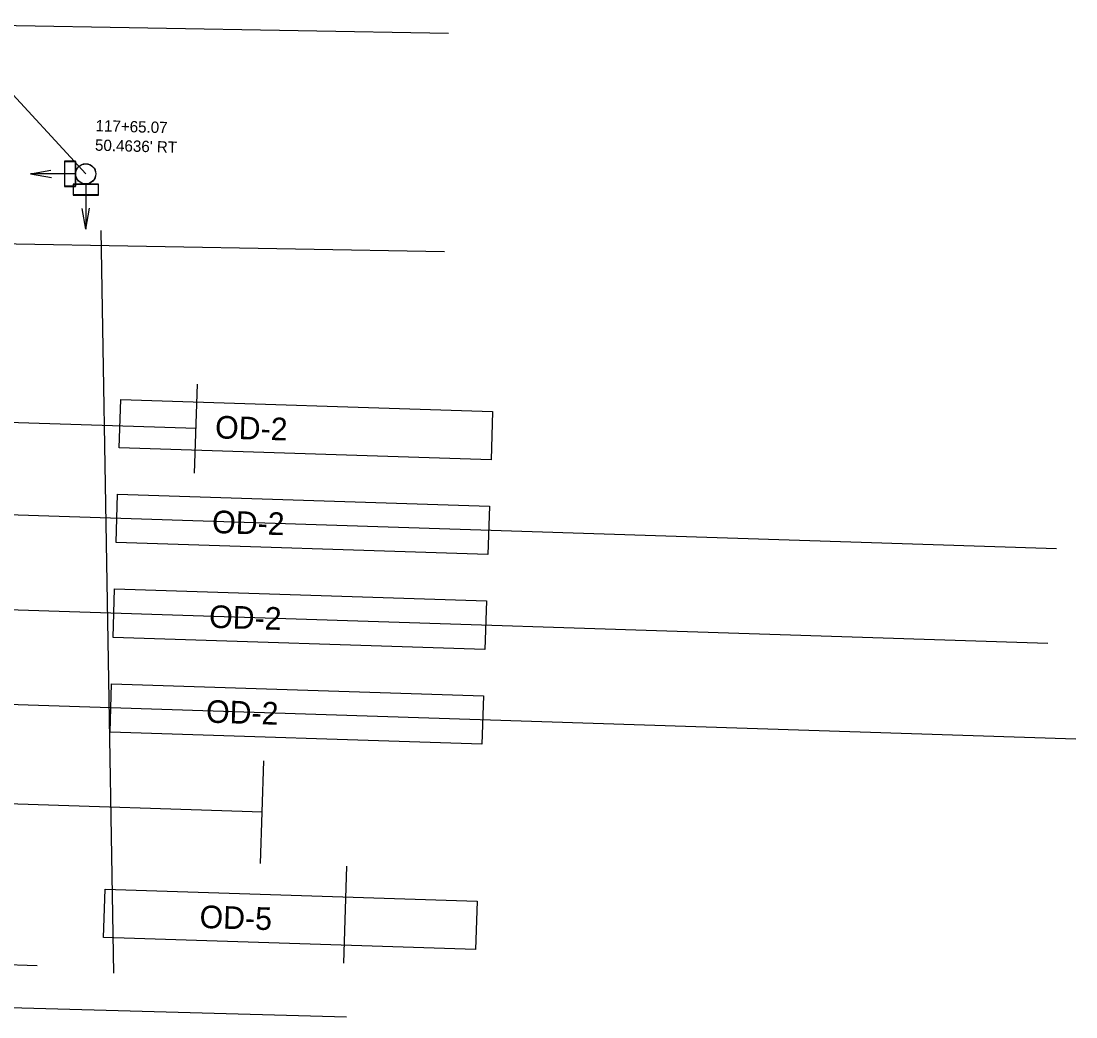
# Model space of a CAD drawing. Extents: x 925524 to 926006, y 853415 to 857998.
# Drawn here: x 925876.1 to 926006.5, y 853550.5 to 853673.7 of the extents above; entities that cross this region are included whole.
import ezdxf

# ---------------------------------------------------------------- set-up
doc = ezdxf.new("R2010")
doc.units = 0
for name, color, linetype in [('ConduitOT', 7, 'Continuous'), ('ConstLines', 7, 'Continuous'), ('NonPlottingEle_dp', 7, 'Continuous'), ('PedHead', 7, 'Continuous'), ('TextMinor', 7, 'Continuous')]:
    doc.layers.add(name, color=color, linetype=linetype)

msp = doc.modelspace()

# ---------------------------------------------------------------- linework, layer by layer
at = {"layer": 'ConduitOT'}
msp.add_line((925871.43, 853668.55), (925884.05, 853654.81), dxfattribs=at)
at = {"layer": 'ConstLines'}
msp.add_line((925885.91, 853647.82), (925887.47, 853555.95), dxfattribs=at)
at = {"layer": 'NonPlottingEle_dp'}
for p, q in [((925928.9, 853672.19), (925843.53, 853673.72)), ((925928.42, 853645.19), (925843.05, 853646.72)), ((925897.69, 853623.31), (925711.32, 853629.35)), ((925897.51, 853617.8), (925897.87, 853628.82)), ((926004.06, 853608.44), (925681.22, 853618.9)), ((926002.97, 853596.74), (925680.13, 853607.2)), ((926006.46, 853584.89), (925700.62, 853594.79)), ((925905.88, 853575.86), (925712.86, 853582.11)), ((925905.67, 853569.52), (925906.08, 853582.2)), ((925916.3, 853569.19), (925915.91, 853557.2)), ((925715.34, 853562.18), (925878.03, 853556.91)), ((925704.91, 853556.44), (925916.29, 853550.54))]:
    msp.add_line(p, q, dxfattribs=at)
at = {"layer": 'PedHead'}
for p, q in [((925882.79, 853656.39), (925881.42, 853656.39)), ((925881.42, 853656.39), (925881.42, 853653.26)), ((925881.45, 853653.3), (925881.45, 853656.35)), ((925881.45, 853656.35), (925882.79, 853656.35)), ((925882.79, 853653.26), (925882.79, 853656.39)), ((925882.79, 853656.35), (925882.79, 853653.3)), ((925877.22, 853654.82), (925879.75, 853655.27)), ((925882.79, 853654.82), (925877.22, 853654.82)), ((925877.22, 853654.82), (925879.82, 853654.36)), ((925881.42, 853653.26), (925882.79, 853653.26)), ((925882.79, 853653.3), (925881.45, 853653.3)), ((925885.61, 853653.56), (925882.48, 853653.56)), ((925882.48, 853653.56), (925882.48, 853652.19)), ((925882.52, 853652.22), (925882.52, 853653.56)), ((925882.52, 853653.56), (925885.57, 853653.56)), ((925884.05, 853653.56), (925884.05, 853647.99)), ((925885.57, 853653.56), (925885.57, 853652.22)), ((925885.61, 853652.19), (925885.61, 853653.56)), ((925882.48, 853652.19), (925885.61, 853652.19)), ((925885.57, 853652.22), (925882.52, 853652.22)), ((925884.05, 853647.99), (925883.6, 853650.52)), ((925884.05, 853647.99), (925884.51, 853650.59))]:
    msp.add_line(p, q, dxfattribs=at)
for centre in [(925884.04, 853654.82), (925884.05, 853654.81)]:
    msp.add_circle(centre, 1.25, dxfattribs=at)
at = {"layer": 'TextMinor'}
for points in [[(925934.34, 853625.42), (925934.15, 853619.43), (925888.17, 853620.92), (925888.37, 853626.91), (925934.34, 853625.42)], [(925933.97, 853613.71), (925933.77, 853607.72), (925887.8, 853609.21), (925887.99, 853615.2), (925933.97, 853613.71)], [(925933.59, 853601.99), (925933.4, 853595.99), (925887.42, 853597.48), (925887.62, 853603.48), (925933.59, 853601.99)], [(925933.22, 853590.26), (925933.03, 853584.27), (925887.05, 853585.75), (925887.25, 853591.75), (925933.22, 853590.26)], [(925932.42, 853564.86), (925932.22, 853558.87), (925886.25, 853560.36), (925886.44, 853566.35), (925932.42, 853564.86)]]:
    msp.add_lwpolyline(points, dxfattribs=at)

# ---------------------------------------------------------------- texts
at = {"layer": 'NonPlottingEle_dp'}
for s, p in [('117+65.07', (925885.25, 853660.09)), ("50.4636' RT", (925885.18, 853657.69))]:
    msp.add_text(s, height=1.4, rotation=358.3939, dxfattribs=at).set_placement(p)
at = {"layer": 'TextMinor'}
for s, p in [('OD-2', (925900.01, 853622.11)), ('OD-2', (925899.64, 853610.4)), ('OD-2', (925899.27, 853598.68)), ('OD-2', (925898.89, 853586.95)), ('OD-5', (925898.09, 853561.55))]:
    msp.add_text(s, height=2.8, rotation=358.2234, dxfattribs=at).set_placement(p)

doc.saveas('drawing.dxf')
